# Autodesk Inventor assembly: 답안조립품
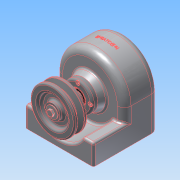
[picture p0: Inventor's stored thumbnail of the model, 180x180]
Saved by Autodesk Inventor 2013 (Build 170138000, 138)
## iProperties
Created: 2015-02
Part Number: 답안조립품
Document SubType Name: Assembly
Designer: Administrator
Author: Administrator
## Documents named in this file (14)
- C:\DOCUME~1\ADMINI~1\LOCALS~1\Temp\BNZ.54dc4a6ab1e022\답안조립품.iam
- C:\Documents and Settings\Administrator\바탕 화면\450214V1028\1-본체.ipt
- C:\Documents and Settings\Administrator\바탕 화면\450214V1028\베어링 6001.ipt
- C:\Documents and Settings\Administrator\바탕 화면\450214V1028\축.ipt
- C:\Documents and Settings\Administrator\바탕 화면\450214V1028\키4x4.ipt
- C:\Documents and Settings\Administrator\바탕 화면\450214V1028\키5x5.ipt
- C:\Documents and Settings\Administrator\바탕 화면\450214V1028\스퍼기어.ipt
- C:\Documents and Settings\Administrator\바탕 화면\450214V1028\축커버.ipt
- C:\Documents and Settings\Administrator\바탕 화면\450214V1028\M3x0.5.ipt
- C:\Documents and Settings\Administrator\바탕 화면\450214V1028\4-V-벨트풀리.ipt
- C:\Documents and Settings\Administrator\바탕 화면\450214V1028\M5x0.8.ipt
- M5x0.8.ipt
- C:\Documents and Settings\Administrator\바탕 화면\450214V1028\와샤.ipt
- C:\Documents and Settings\Administrator\바탕 화면\450214V1028\오일실.ipt
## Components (7 placed, 4 different names)
1. 1-본체:1
2. 4-V-벨트풀리:1 — 각도:4
3. M5x0.8:1 — 각도:5
4. M3x0.5:1
5. M3x0.5:2
6. M3x0.5:3
7. M3x0.5:4
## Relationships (2: Angle 2)
- 각도:4 [Angle]: 4-V-벨트풀리:1
- 각도:5 [Angle]: M5x0.8:1
